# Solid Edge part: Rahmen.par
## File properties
Author: Heike
Template: Normal.par
Last saved by: Heike
Revision: 43
Application: Solid Edge
Dichte: 1,024 kg/dm^3
Genauigkeit: 0,990
Material: ABS Plastik, mittelfest
Teilflächenrmatvorlage: Grün (Glas)
Füllformatvorlage: ANSI34(Plastic)
Virtuelle Formatvorlage: Schwarz (hell glänzend)
Coef. of Thermal Exp: 5.8e-05
Thermal Conductivity: 2.0
Specific Heat: 0.0
Modulus of Elasticity: 2275269810.0
Poission's Ratio: 0.4
Yield Stress: 43436969.1
Ultimate Stress: 0.0
Elongation: 0.0
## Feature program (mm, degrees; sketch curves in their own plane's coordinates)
sketch for "unnamed Protrusion 1" plane through (0, 0, 0) normal (0, 0, 1) x-axis (1, 0, 0)
  line (-30, 30) -> (0, 30)
  line (0, 30) -> (0, 0)
  line (0, 0) -> (-30, 0)
  line (-30, 0) -> (-30, 30)
  dimension (linear) = 30
extrude "unnamed Protrusion 1" add finite 9.2 along +normal
fillet "Verrundung" radius 8
logasc func "Freiheit"  LipOrGrooveWidth = 1 mm; LipOrGrooveHeight = 10 mm
sketch for "Dünn_5" plane through (-14.5, 14.5, 9.2) normal (0, 0, 1) x-axis (1, 0, 0)
extrude "Dünn_5" cut finite 4 along -normal
sketch for "unnamed Cutout 1" plane through (0, 0, 5.2) normal (0, 0, 1) x-axis (1, 0, 0)
  line (-7.05, 7.62) -> (7.05, 7.62)
  line (7.05, 7.62) -> (7.05, -7.62)
  line (7.05, -7.62) -> (-7.05, -7.62)
  line (-7.05, -7.62) -> (-7.05, 7.62)
  dimension (linear) = 7.05
  dimension (linear) = 7.05
extrude "unnamed Cutout 1" cut through along -normal
sketch for "Dünn_1" plane through (-12, 12, 5.2) normal (0, 0, 1) x-axis (1, 0, 0)
  line (3.95, -3.38) -> (12, -3.38)
  line (12, -3.38) -> (12, -12)
  line (12, -12) -> (3.95, -12)
  line (3.95, -12) -> (3.95, -3.38)
extrude "Dünn_1" cut finite 4 along -normal
sketch for "unnamed Cutout 2" #1 plane through (0, 0, 5.2) normal (0, 0, 1) x-axis (1, 0, 0)
  line (-8.05, 24) -> (-8.05, 10.62)
  line (-8.05, 10.62) -> (0, 10.62)
  line (0, 10.62) -> (0, 24)
  line (-8.05, 24) -> (0, 24)
sketch for "unnamed Cutout 2" #2 plane through (0, 0, 5.2) normal (0, 0, 1) x-axis (1, 0, 0)
  line (-24, 8.62) -> (-10.05, 8.62)
  line (-10.05, 8.62) -> (-10.05, 0)
  line (-24, 0) -> (-10.05, 0)
  line (-24, 0) -> (-24, 8.62)
sketch for "unnamed Cutout 2" #3 plane through (0, 0, 5.2) normal (0, 0, 1) x-axis (1, 0, 0)
  line (-10.05, 24) -> (-10.05, 10.62)
  line (-10.05, 10.62) -> (-24, 10.62)
  line (-24, 10.62) -> (-24, 15)
  line (-24, 15) -> (-22, 15)
  arc centre (-22, 22) radius 7 from (-22, 15) to (-15, 22) ccw
  line (-15, 22) -> (-15, 24)
  line (-15, 24) -> (-10.05, 24)
extrude "unnamed Cutout 2" cut through along -normal
sketch for "Befestigung" plane through (-14.5, 14.5, 0) normal (0, 0, -1) x-axis (-1, 0, 0)
  hole centre (7.5, 7.5) bore radius 2
hole "Befestigung" diameter 4 through
sketch for "Klebpad" plane through (0, 14.4994, 9.2) normal (0, 0, 1) x-axis (1, 0, 0)
  line (-29, 0.5006) -> (-15, 0.5006)
  line (-15, 0.5006) -> (-15, 14.5006)
  line (-15, 14.5006) -> (-29, 14.5006)
  line (-29, 14.5006) -> (-29, 0.5006)
extrude "Klebpad" cut finite 0.8 along -normal
mirror "unnamed Mirror 1" of "unnamed Cutout 2", "Dünn_1", "unnamed Cutout 1", "Dünn_5", "Freiheit", "Verrundung", "unnamed Protrusion 1", "Befestigung", "Klebpad" about plane through (0, 0, 0) normal (0, -1, 0)
extrude "unnamed Protrusion 2" add finite 9.2
fillet "unnamed Round 1"
logasc func "unnamed LOGAscFunc 1"
extrude "unnamed Cutout 3" cut finite 4
extrude "unnamed Cutout 4" cut through
extrude "unnamed Cutout 5" cut finite 4
extrude "unnamed Cutout 6" cut through
hole "unnamed Hole 1" through
extrude "unnamed Cutout 7" cut finite 0.8
sketch for "Raste" plane through (-29, 0, 4.6) normal (-1, 0, 0) x-axis (0, 1, 0)
  circle centre (0, 0.4) radius 2.6
extrude "Raste" cut finite 1.2 along -normal
mirror "unnamed Mirror 2" of "unnamed Protrusion 1", "Verrundung", "Freiheit", "Dünn_5", "unnamed Cutout 1", "unnamed Cutout 2", "Raste", "Dünn_1", "unnamed Mirror 1", "Befestigung", "Klebpad" about plane through (0, 0, 0) normal (1, 0, 0)
extrude "unnamed Protrusion 3" add finite 9.2
fillet "unnamed Round 2"
logasc func "unnamed LOGAscFunc 2"
extrude "unnamed Cutout 8" cut finite 4
extrude "unnamed Cutout 9" cut through
extrude "unnamed Cutout 10" cut finite 4
extrude "unnamed Cutout 11" cut through
hole "unnamed Hole 2" through
extrude "unnamed Cutout 12" cut finite 0.8
extrude "unnamed Protrusion 4" add finite 9.2
fillet "unnamed Round 3"
logasc func "unnamed LOGAscFunc 3"
extrude "unnamed Cutout 13" cut finite 4
extrude "unnamed Cutout 14" cut through
extrude "unnamed Cutout 15" cut finite 4
extrude "unnamed Cutout 16" cut through
hole "unnamed Hole 3" through
extrude "unnamed Cutout 17" cut finite 0.8
extrude "unnamed Cutout 18" cut finite 1.2
Other named dimensions: "Bohrung5": Diameter = 5 mm; CounterBoreDiameter = 10 mm | "LED": Diameter = 5 mm; CounterBoreDiameter = 7 mm
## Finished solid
Body 1: solid body, 83 faces, 236 edges, 144 vertices.
  Faces by surface: plane 65, cylinder 14, cone 4
  Edges by curve: line 204, circle 32
Bounding box of the edges (mm): 58.000 x 58.000 x 9.200, from (-29, -29, 0) to (29, 29, 9.2).
Cylindrical faces by radius (mm): R2 x4, R2.6 x2, R7 x8
Conical faces (half-angle, radius in mm at the cone's reference point): 45 deg R4 x4
Planar faces by outward normal: +x 14, +y 13, +z 10, -x 14, -y 13, -z 1
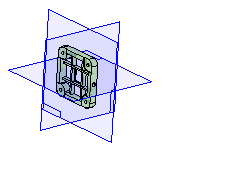
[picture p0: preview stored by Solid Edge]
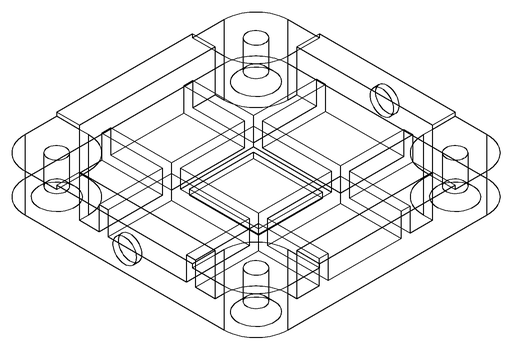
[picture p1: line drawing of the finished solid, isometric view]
